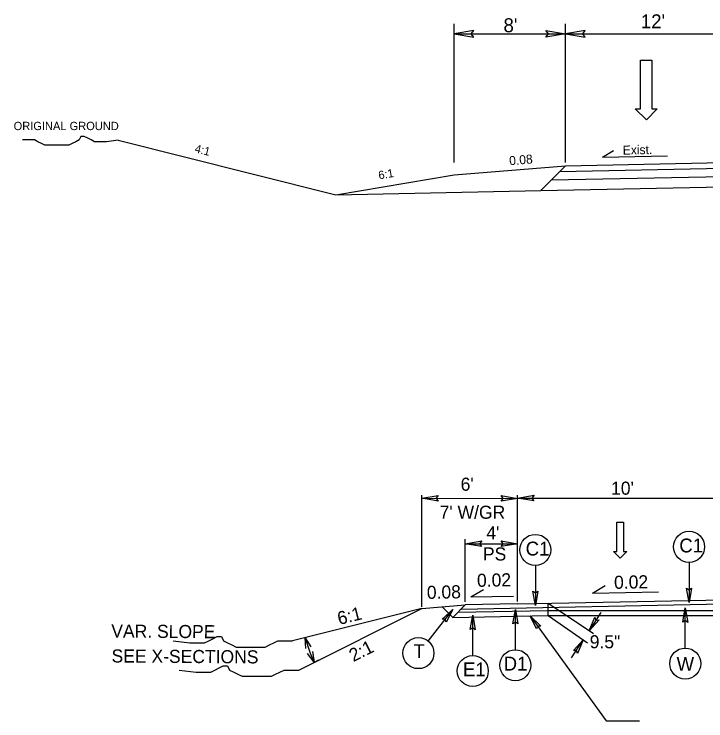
# Model space of a CAD drawing. Extents: x 2111095 to 2115970, y 670428 to 672393.
# Drawn here: x 2112273.2 to 2112322.8, y 670427.8 to 670478.6 of the extents above; entities that cross this region are included whole.
import ezdxf

# ---------------------------------------------------------------- set-up
doc = ezdxf.new("R2010")
doc.units = 0
for name, color, linetype in [('Old_Level_1', 7, 'Continuous'), ('Old_Level_11', 7, 'Continuous'), ('Old_Level_2', 7, 'Continuous'), ('Old_Level_20', 7, 'Continuous'), ('Old_Level_3', 7, 'Continuous'), ('Prop Dimension', 7, 'Continuous'), ('Prop Dimension Text', 7, 'Continuous'), ('Prop Lane Arrow CELL', 7, 'Continuous'), ('Prop Leader Line Medium', 7, 'Continuous'), ('Typical Hinge Slope Arterial CELL', 7, 'Continuous'), ('Typical ID Circle CELL', 7, 'Continuous'), ('Typical Pavement Slope CELL', 7, 'Continuous'), ('Typical Pavement Slope Information CELL', 7, 'Continuous'), ('Typical Shoulder Slope CELL', 7, 'Continuous'), ('Typical Shoulder Slope Information CELL', 7, 'Continuous'), ('Typical Terminator CELL', 7, 'Continuous'), ('Typical Text ID Circle CELL', 7, 'Continuous')]:
    doc.layers.add(name, color=color, linetype=linetype)

msp = doc.modelspace()

# ---------------------------------------------------------------- linework, layer by layer
at = {"layer": 'Old_Level_1'}
for p, q in [((2112302.472, 670435.907), (2112305.593, 670436.166)), ((2112304.695, 670435.268), (2112305.593, 670436.166)), ((2112305.29, 670435.864), (2112324.117, 670436.238)), ((2112309.343, 670436.241), (2112305.593, 670436.166)), ((2112309.343, 670436.241), (2112324.117, 670436.535)), ((2112311.542, 670435.41), (2112311.542, 670436.285)), ((2112302.472, 670435.907), (2112293.206, 670433.591)), ((2112293.645, 670431.494), (2112302.472, 670435.907)), ((2112303.935, 670436.028), (2112304.695, 670435.268)), ((2112305.066, 670435.639), (2112311.542, 670435.768)), ((2112311.542, 670435.768), (2112324.117, 670435.768)), ((2112304.7, 670435.274), (2112311.542, 670435.41)), ((2112311.542, 670435.41), (2112324.117, 670435.41))]:
    msp.add_line(p, q, dxfattribs=at)
for points in [[(2112284.643, 670433.592), (2112285.844, 670433.442), (2112286.145, 670433.442), (2112286.596, 670433.442), (2112286.896, 670433.442), (2112287.197, 670433.592), (2112287.497, 670433.742), (2112287.798, 670433.893), (2112288.098, 670433.893), (2112288.249, 670433.591), (2112288.549, 670433.442), (2112288.85, 670433.291), (2112289.15, 670433.141), (2112289.45, 670433.141), (2112289.751, 670433.141), (2112290.051, 670433.141), (2112290.352, 670433.141), (2112290.652, 670433.141), (2112290.952, 670433.141), (2112291.253, 670433.141), (2112291.553, 670433.291), (2112291.854, 670433.442), (2112292.154, 670433.591), (2112292.605, 670433.591), (2112292.906, 670433.591), (2112293.206, 670433.591)], [(2112285.082, 670431.495), (2112286.283, 670431.345), (2112286.584, 670431.345), (2112287.035, 670431.345), (2112287.335, 670431.345), (2112287.636, 670431.495), (2112287.936, 670431.645), (2112288.237, 670431.796), (2112288.537, 670431.796), (2112288.688, 670431.494), (2112288.988, 670431.345), (2112289.288, 670431.194), (2112289.589, 670431.044), (2112289.889, 670431.044), (2112290.19, 670431.044), (2112290.49, 670431.044), (2112290.79, 670431.044), (2112291.091, 670431.044), (2112291.391, 670431.044), (2112291.692, 670431.044), (2112291.992, 670431.194), (2112292.293, 670431.345), (2112292.593, 670431.494), (2112293.044, 670431.494), (2112293.345, 670431.494), (2112293.645, 670431.494)]]:
    msp.add_lwpolyline(points, dxfattribs=at)
at = {"layer": 'Old_Level_11'}
for p, q in [((2112302.467, 670436.025), (2112302.468, 670444.043)), ((2112302.468, 670443.813), (2112309.344, 670443.812)), ((2112309.343, 670436.412), (2112309.344, 670444.042)), ((2112309.343, 670436.616), (2112309.344, 670444.042)), ((2112309.344, 670443.832), (2112324.118, 670443.831)), ((2112305.593, 670436.399), (2112305.593, 670440.874)), ((2112305.593, 670440.556), (2112309.343, 670440.556)), ((2112321.64, 670439.221), (2112321.64, 670436.342)), ((2112310.618, 670438.998), (2112310.618, 670436.119)), ((2112302.935, 670433.571), (2112304.706, 670435.848)), ((2112309.183, 670432.953), (2112309.183, 670435.836)), ((2112306.13, 670432.539), (2112306.13, 670435.423)), ((2112294.778, 670432.07), (2112295.101, 670432.232))]:
    msp.add_line(p, q, dxfattribs=at)
for points in [[(2112310.796, 670437.15), (2112310.618, 670436.119), (2112310.435, 670437.156), (2112310.618, 670437.024)], [(2112321.818, 670437.373), (2112321.64, 670436.342), (2112321.457, 670437.379), (2112321.64, 670437.247)], [(2112303.933, 670435.143), (2112304.706, 670435.848), (2112304.215, 670434.917), (2112304.151, 670435.133)], [(2112309.005, 670434.805), (2112309.183, 670435.836), (2112309.366, 670434.799), (2112309.183, 670434.931)], [(2112305.952, 670434.391), (2112306.13, 670435.423), (2112306.313, 670434.385), (2112306.13, 670434.517)], [(2112310.708, 670434.443), (2112310.25, 670435.384), (2112311.004, 670434.649), (2112310.778, 670434.649)]]:
    msp.add_lwpolyline(points, close=True, dxfattribs=at)
for points in [[(2112294.147, 670433.043), (2112294.113, 670433.815), (2112294.507, 670433.15)], [(2112294.63, 670432.825), (2112294.766, 670432.064), (2112294.288, 670432.672)]]:
    msp.add_lwpolyline(points, dxfattribs=at)
for centre in [(2112310.618, 670440.112), (2112321.64, 670440.334), (2112302.232, 670432.707), (2112306.13, 670431.425), (2112309.183, 670431.839)]:
    msp.add_circle(centre, 1.114, dxfattribs=at)
msp.add_arc((2112302.446, 670435.916), 8.592, 194.187, 206.6371, dxfattribs=at)
at = {"layer": 'Old_Level_2'}
for p, q in [((2112314.725, 670437.014), (2112315.632, 670437.562)), ((2112305.984, 670436.734), (2112306.891, 670437.282)), ((2112314.725, 670437.014), (2112319.454, 670437.108)), ((2112305.984, 670436.734), (2112309.056, 670436.795))]:
    msp.add_line(p, q, dxfattribs=at)
at = {"layer": 'Old_Level_3'}
for p, q in [((2112310.25, 670435.384), (2112315.699, 670427.847)), ((2112315.699, 670427.847), (2112318.09, 670427.847))]:
    msp.add_line(p, q, dxfattribs=at)
at = {"layer": 'Prop Dimension'}
for p, q in [((2112311.542, 670436.285), (2112314.788, 670434.109)), ((2112315.316, 670435.619), (2112314.477, 670434.318)), ((2112311.542, 670435.41), (2112314.361, 670433.449)), ((2112313.214, 670432.362), (2112314.053, 670433.663))]:
    msp.add_line(p, q, dxfattribs=at)
at = {"layer": 'Prop Lane Arrow CELL'}
for p, q in [((2112318.155, 670471.757), (2112318.155, 670475.257)), ((2112318.155, 670475.257), (2112318.98, 670475.257)), ((2112318.98, 670475.257), (2112318.98, 670471.757)), ((2112318.58, 670470.969), (2112317.78, 670471.757)), ((2112317.78, 670471.757), (2112318.155, 670471.757)), ((2112319.355, 670471.757), (2112318.58, 670470.969)), ((2112318.98, 670471.757), (2112319.355, 670471.757)), ((2112316.451, 670439.988), (2112316.451, 670442.114)), ((2112316.451, 670442.114), (2112316.952, 670442.114)), ((2112316.952, 670442.114), (2112316.952, 670439.988)), ((2112316.709, 670439.509), (2112316.223, 670439.988)), ((2112316.223, 670439.988), (2112316.451, 670439.988)), ((2112317.18, 670439.988), (2112316.709, 670439.509)), ((2112316.952, 670439.988), (2112317.18, 670439.988))]:
    msp.add_line(p, q, dxfattribs=at)
at = {"layer": 'Prop Leader Line Medium'}
for p, q in [((2112304.792, 670467.918), (2112304.792, 670477.868)), ((2112312.792, 670467.918), (2112312.792, 670477.868)), ((2112304.792, 670477.147), (2112344.792, 670477.147)), ((2112312.792, 670467.678), (2112311.006, 670465.892)), ((2112312.384, 670467.269), (2112324.792, 670467.518)), ((2112312.792, 670467.678), (2112324.792, 670467.918)), ((2112311.771, 670466.657), (2112324.812, 670466.918)), ((2112311.006, 670465.892), (2112324.792, 670466.167))]:
    msp.add_line(p, q, dxfattribs=at)
at = {"layer": 'Typical Hinge Slope Arterial CELL'}
for p, q in [((2112280.693, 670469.502), (2112290.311, 670467.097)), ((2112290.311, 670467.097), (2112296.31, 670465.598)), ((2112296.31, 670465.598), (2112304.792, 670467.011))]:
    msp.add_line(p, q, dxfattribs=at)
msp.add_lwpolyline([(2112280.693, 670469.502), (2112279.872, 670469.4), (2112279.626, 670469.4), (2112279.256, 670469.4), (2112279.009, 670469.4), (2112278.763, 670469.522), (2112278.517, 670469.646), (2112278.27, 670469.77), (2112278.024, 670469.77), (2112277.9, 670469.522), (2112277.654, 670469.4), (2112277.407, 670469.276), (2112277.161, 670469.153), (2112276.915, 670469.153), (2112276.668, 670469.153), (2112276.422, 670469.153), (2112276.176, 670469.153), (2112275.929, 670469.153), (2112275.683, 670469.153), (2112275.437, 670469.153), (2112275.19, 670469.276), (2112274.944, 670469.4), (2112274.697, 670469.522), (2112274.327, 670469.522), (2112274.081, 670469.522), (2112273.835, 670469.522)], dxfattribs=at)
at = {"layer": 'Typical ID Circle CELL'}
msp.add_line((2112321.373, 670433.073), (2112321.373, 670435.952), dxfattribs=at)
msp.add_circle((2112321.373, 670431.959), 1.114, dxfattribs=at)
at = {"layer": 'Typical Pavement Slope CELL'}
msp.add_line((2112296.31, 670465.598), (2112311.006, 670465.892), dxfattribs=at)
at = {"layer": 'Typical Pavement Slope Information CELL'}
for q in [(2112316.222, 670468.769), (2112320.1, 670468.389)]:
    msp.add_line((2112315.439, 670468.295), q, dxfattribs=at)
at = {"layer": 'Typical Shoulder Slope CELL'}
msp.add_line((2112304.792, 670467.011), (2112312.792, 670467.678), dxfattribs=at)
at = {"layer": 'Typical Terminator CELL'}
for points in [[(2112306.198, 670477.389), (2112304.792, 670477.147), (2112306.206, 670476.897), (2112306.026, 670477.147)], [(2112311.382, 670477.389), (2112312.788, 670477.147), (2112311.374, 670476.897), (2112311.553, 670477.147)], [(2112314.194, 670477.389), (2112312.788, 670477.147), (2112314.201, 670476.897), (2112314.022, 670477.147)], [(2112303.64, 670443.611), (2112302.468, 670443.813), (2112303.646, 670444.021), (2112303.497, 670443.813)], [(2112308.172, 670444.014), (2112309.344, 670443.812), (2112308.165, 670443.604), (2112308.315, 670443.812)], [(2112310.515, 670443.63), (2112309.344, 670443.832), (2112310.522, 670444.04), (2112310.372, 670443.832)], [(2112306.765, 670440.354), (2112305.593, 670440.556), (2112306.771, 670440.764), (2112306.622, 670440.556)], [(2112308.172, 670440.758), (2112309.343, 670440.556), (2112308.165, 670440.347), (2112308.315, 670440.556)], [(2112321.196, 670434.92), (2112321.373, 670435.952), (2112321.557, 670434.914), (2112321.373, 670435.046)], [(2112315.185, 670435.088), (2112314.477, 670434.318), (2112314.885, 670435.289), (2112314.967, 670435.078)], [(2112313.345, 670432.893), (2112314.053, 670433.663), (2112313.645, 670432.692), (2112313.562, 670432.903)]]:
    msp.add_lwpolyline(points, close=True, dxfattribs=at)

# ---------------------------------------------------------------- texts
at = {"layer": 'Old_Level_1'}
for s, height, rotation, p in [('6:1', 0.9391, 14.0309, (2112296.553, 670434.721)), ('VAR. SLOPE', 0.9391, 359.6033, (2112280.203, 670433.824)), ('2:1', 0.9391, 26.5607, (2112297.56, 670432.055)), ('SEE X-SECTIONS', 0.93912, 359.6033, (2112280.221, 670432.039))]:
    msp.add_text(s, height=height, rotation=rotation, dxfattribs=at).set_placement(p)
at = {"layer": 'Old_Level_11'}
for s, p in [("6'", (2112305.261, 670444.358)), ("10'", (2112316.048, 670444.072)), ("7' W/GR", (2112303.753, 670442.346)), ("4'", (2112307.103, 670440.865)), ('PS', (2112306.859, 670439.353))]:
    msp.add_text(s, height=0.9391, rotation=359.9946, dxfattribs=at).set_placement(p)
at = {"layer": 'Old_Level_20'}
for s, height, p in [('C1', 0.9971, (2112309.922, 670439.708)), ('C1', 0.9971, (2112320.943, 670439.931)), ('T', 0.997, (2112301.881, 670432.35)), ('E1', 0.9971, (2112305.427, 670431.043)), ('D1', 0.9971, (2112308.345, 670431.457))]:
    msp.add_text(s, height=height, dxfattribs=at).set_placement(p)
at = {"layer": 'Old_Level_3'}
for s, p in [('0.02', (2112306.442, 670437.456)), ('0.02', (2112316.271, 670437.314)), ('0.08', (2112302.845, 670436.594))]:
    msp.add_text(s, height=0.9391, rotation=1.1404, dxfattribs=at).set_placement(p)
at = {"layer": 'Prop Dimension Text'}
msp.add_text('9.5"', height=0.9391, rotation=360, dxfattribs=at).set_placement((2112314.518, 670433.053))
at = {"layer": 'Prop Leader Line Medium'}
for s, p in [("8'", (2112308.334, 670477.255)), ("12'", (2112318.18, 670477.537))]:
    msp.add_text(s, height=1, rotation=360, dxfattribs=at).set_placement(p)
at = {"layer": 'Typical Hinge Slope Arterial CELL'}
for s, height, rotation, p in [('ORIGINAL GROUND', 0.59365, 360, (2112273.201, 670470.232)), ('4:1', 0.5936, 345.9638, (2112286.147, 670468.647)), ('6:1', 0.5937, 9.4623, (2112299.41, 670466.692))]:
    msp.add_text(s, height=height, rotation=rotation, dxfattribs=at).set_placement(p)
at = {"layer": 'Typical Pavement Slope Information CELL'}
msp.add_text('Exist.', height=0.6476, rotation=1.1457, dxfattribs=at).set_placement((2112316.892, 670468.471))
at = {"layer": 'Typical Shoulder Slope Information CELL'}
msp.add_text('0.08', height=0.6476, rotation=4.7615, dxfattribs=at).set_placement((2112308.771, 670467.707))
at = {"layer": 'Typical Text ID Circle CELL'}
msp.add_text('W', height=0.997, dxfattribs=at).set_placement((2112320.747, 670431.438))

doc.saveas('drawing.dxf')
